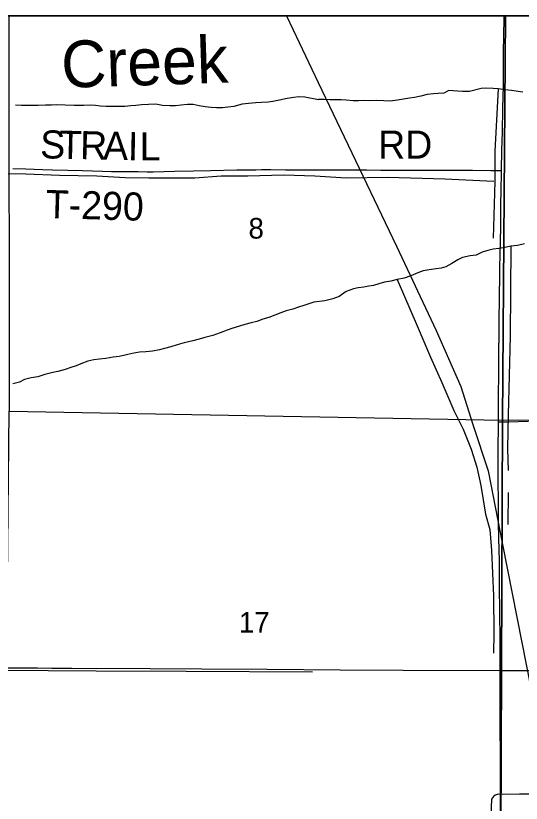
# Model space of a CAD drawing. Extents: x 0 to 34, y 0 to 22.
# Drawn here: x 2.522 to 3.546, y 19.306 to 20.9 of the extents above; entities that cross this region are included whole.
import ezdxf

# ---------------------------------------------------------------- set-up
doc = ezdxf.new("R2010")
doc.units = 0
for name, color, linetype in [('GM_X_City_Street', 7, 'Continuous'), ('GM_X_County_Road', 7, 'Continuous'), ('GM_X_Minor_River', 7, 'Continuous'), ('GM_X_Minor_River_Text', 7, 'Continuous'), ('GM_X_Rail_Line', 7, 'Continuous'), ('GM_X_Section', 7, 'Continuous'), ('GM_X_Section_Text', 7, 'Continuous'), ('GM_X_Township_Road', 7, 'Continuous'), ('GM_X_Township_Road_Text', 7, 'Continuous'), ('GM_X_US_Route', 7, 'Continuous'), ('SH_Cut_Line', 7, 'Continuous'), ('SH_Data', 7, 'Continuous')]:
    doc.layers.add(name, color=color, linetype=linetype)

msp = doc.modelspace()

# ---------------------------------------------------------------- linework, layer by layer
at = {"layer": 'GM_X_City_Street'}
for points in [[(3.5146, 20.9), (2.5083, 20.9), (2.509, 20.0994), (3.5083, 20.0811)], [(4.528, 20.9), (3.5146, 20.9), (3.5083, 20.0811), (4.5187, 20.0828)]]:
    msp.add_lwpolyline(points, close=True, dxfattribs=at)
at = {"layer": 'GM_X_County_Road'}
for points in [[(3.5065, 20.5865), (3.5072, 20.628), (3.5081, 20.6646), (3.5093, 20.7131), (3.5101, 20.7579), (3.5102, 20.7791), (3.5104, 20.8002), (3.5107, 20.8313), (3.511, 20.8549), (3.5119, 20.9)], [(3.5002, 20.078), (3.5002, 20.0911), (3.5006, 20.1446), (3.5007, 20.1608), (3.5008, 20.1788), (3.501, 20.2242), (3.5014, 20.2509), (3.5018, 20.2926), (3.5021, 20.3187), (3.503, 20.3868), (3.5039, 20.4197), (3.5043, 20.4409), (3.5047, 20.4757), (3.5053, 20.5117), (3.5059, 20.5528), (3.5063, 20.5758), (3.5065, 20.5865)], [(3.5035, 19.5744), (3.5035, 19.5826), (3.5034, 19.6354), (3.5029, 19.6951), (3.5023, 19.7424), (3.5024, 19.7585), (3.5022, 19.7958), (3.5011, 19.8425), (3.5006, 19.8742), (3.5001, 19.904), (3.4997, 19.9712), (3.4999, 20.0302), (3.5001, 20.0644), (3.5002, 20.078)], [(3.5048, 19.0707), (3.5048, 19.0947), (3.5048, 19.104), (3.5048, 19.173), (3.5048, 19.2159), (3.5047, 19.2551), (3.5045, 19.2887), (3.5044, 19.3154), (3.5042, 19.3353), (3.504, 19.3713), (3.504, 19.408), (3.5037, 19.4559), (3.5038, 19.4764), (3.5035, 19.5168), (3.5037, 19.5347), (3.5035, 19.5565), (3.5035, 19.5744)]]:
    msp.add_lwpolyline(points, dxfattribs=at)
at = {"layer": 'GM_X_Minor_River'}
for points in [[(3.5496, 20.7454), (3.5269, 20.7486), (3.5133, 20.7501), (3.4997, 20.7519), (3.4892, 20.7529), (3.4748, 20.7537), (3.4649, 20.7524), (3.4413, 20.7469), (3.4273, 20.7468), (3.4174, 20.7475), (3.3997, 20.7487), (3.3897, 20.7436), (3.3783, 20.7423), (3.3688, 20.7418), (3.3555, 20.7406), (3.343, 20.7371), (3.33, 20.7344), (3.3198, 20.7331), (3.2954, 20.7292), (3.281, 20.7272), (3.2681, 20.7279), (3.2534, 20.7283), (3.2397, 20.7279), (3.2272, 20.7282), (3.217, 20.7276), (3.206, 20.7275), (3.1917, 20.7294), (3.1814, 20.7296), (3.1712, 20.7295), (3.1587, 20.7298), (3.147, 20.7305), (3.136, 20.7307)], [(3.4997, 20.7519), (3.4928, 20.6257), (3.4928, 20.5646), (3.4896, 20.4501)], [(2.5221, 20.7194), (2.5342, 20.7187), (2.5463, 20.7187), (2.5581, 20.7191), (2.5676, 20.7188), (2.5828, 20.7195), (2.5946, 20.72), (2.6041, 20.7201), (2.6405, 20.719), (2.6507, 20.7191), (2.6602, 20.7192), (2.6732, 20.7196), (2.6841, 20.7189), (2.694, 20.7179), (2.7053, 20.7168), (2.7182, 20.7168), (2.7338, 20.7167), (2.7437, 20.7168), (2.7559, 20.718), (2.7658, 20.7189), (2.7779, 20.7204), (2.7913, 20.7212), (2.8065, 20.7219), (2.82, 20.7188), (2.8348, 20.718), (2.8462, 20.7184), (2.8576, 20.7196), (2.8706, 20.7212), (2.8816, 20.7208), (2.8937, 20.7182), (2.9061, 20.7163), (2.9186, 20.7152), (2.9292, 20.7145), (2.9414, 20.7146), (2.952, 20.7154), (2.9646, 20.7173), (2.9818, 20.7218), (2.994, 20.7233), (3.0085, 20.7241), (3.0203, 20.7252), (3.0336, 20.7256), (3.0435, 20.7272), (3.0565, 20.7299), (3.0721, 20.7333), (3.0859, 20.7355), (3.0958, 20.7368), (3.1082, 20.7356), (3.136, 20.7307)], [(3.1282, 20.5752), (3.0655, 20.5771), (2.9928, 20.5751), (2.9386, 20.5755), (2.8853, 20.5713), (2.8318, 20.5713), (2.7919, 20.571), (2.7441, 20.5719), (2.6865, 20.5751), (2.6114, 20.5765), (2.5431, 20.5796), (2.4987, 20.5797), (2.4415, 20.5289), (2.224, 20.5306), (2.1, 20.5313)], [(3.4905, 20.5647), (3.3914, 20.569), (3.2764, 20.5729), (3.1915, 20.5711), (3.1282, 20.5752)], [(3.5529, 20.4383), (3.5388, 20.4352), (3.5255, 20.4336), (3.5107, 20.4302), (3.5008, 20.4286), (3.4894, 20.4273), (3.4784, 20.4245), (3.4673, 20.4214), (3.455, 20.4156), (3.4429, 20.414), (3.4273, 20.4106), (3.4177, 20.4059), (3.4058, 20.3986), (3.3938, 20.3917), (3.3839, 20.3893), (3.3737, 20.3876), (3.36, 20.3857), (3.3478, 20.3837), (3.3367, 20.3798), (3.3229, 20.3733), (3.3092, 20.3687), (3.2947, 20.3664), (3.2825, 20.3629), (3.2692, 20.3609), (3.2582, 20.357), (3.2471, 20.3539), (3.2376, 20.3526)], [(3.5255, 20.4336), (3.5237, 20.2511), (3.5201, 20.0922), (3.5188, 20.0243), (3.5199, 19.9795)], [(3.2947, 20.3664), (3.3356, 20.2724), (3.3628, 20.2087), (3.3854, 20.1577), (3.4097, 20.101), (3.4289, 20.0629), (3.4449, 20.0227), (3.4561, 19.9864), (3.4643, 19.949), (3.4742, 19.891), (3.4825, 19.8601), (3.4864, 19.8175), (3.4898, 19.7259), (3.4905, 19.6493), (3.4899, 19.6094)], [(3.2376, 20.3526), (3.2273, 20.3509), (3.2163, 20.3489), (3.2068, 20.3469), (3.1919, 20.3415), (3.1776, 20.332), (3.165, 20.3273), (3.1483, 20.3232), (3.126, 20.3199)], [(3.126, 20.3199), (3.1164, 20.3168), (3.1057, 20.3137), (3.095, 20.3098), (3.0835, 20.3063), (3.0701, 20.3025), (3.0597, 20.2986), (3.0471, 20.2937), (3.0348, 20.2895), (3.0229, 20.2856), (3.0107, 20.2814), (2.9996, 20.2787), (2.9862, 20.2749), (2.9755, 20.2718), (2.9601, 20.2669), (2.9505, 20.2634), (2.9364, 20.2581), (2.9218, 20.2528), (2.9053, 20.2487), (2.8942, 20.2456), (2.8812, 20.2422), (2.8636, 20.2377), (2.8495, 20.2336), (2.8365, 20.2301), (2.8239, 20.2267), (2.8135, 20.224), (2.7998, 20.2213), (2.7861, 20.2194), (2.7731, 20.2187), (2.7583, 20.2164), (2.7468, 20.2137), (2.7319, 20.2103), (2.7197, 20.2088), (2.7052, 20.2065), (2.6919, 20.205), (2.6805, 20.2034), (2.6682, 20.2008), (2.6544, 20.1951), (2.6448, 20.1915), (2.6341, 20.1877), (2.6226, 20.1838), (2.6077, 20.1801), (2.5973, 20.1777), (2.5817, 20.1736), (2.5675, 20.1694), (2.5534, 20.1668), (2.54, 20.1634), (2.5304, 20.1583), (2.5166, 20.1549)], [(3.52, 19.9351), (3.5195, 19.8702)], [(3.1233, 19.571), (2.8675, 19.5726), (2.6853, 19.5733), (2.4909, 19.5747), (2.3688, 19.5767), (2.1601, 19.5815), (2.1, 19.5823)], [(3.5703, 19.324), (3.5427, 19.3243), (3.5078, 19.3236), (3.4999, 19.3242), (3.4938, 19.3224), (3.4903, 19.3195), (3.4864, 19.3143), (3.4816, 19.1971)]]:
    msp.add_lwpolyline(points, dxfattribs=at)
at = {"layer": 'GM_X_Rail_Line'}
msp.add_lwpolyline([(3.0707, 20.9), (3.1351, 20.7649), (3.2934, 20.4339), (3.3742, 20.2628), (3.4243, 20.1498), (3.4485, 20.0723), (3.4792, 19.9786), (3.5083, 19.83), (3.6846, 18.9371), (3.8463, 18.1103), (4.0848, 16.8935)], dxfattribs=at)
at = {"layer": 'GM_X_Section'}
for points in [[(2.509, 20.0994), (3.5083, 20.0811), (3.5044, 19.0749), (2.4993, 19.0815)], [(4.5187, 20.0828), (4.5106, 19.0706), (3.5044, 19.0749), (3.5083, 20.0811)]]:
    msp.add_lwpolyline(points, close=True, dxfattribs=at)
at = {"layer": 'GM_X_Township_Road'}
for points in [[(2.5165, 20.5907), (2.5426, 20.5899), (2.5767, 20.5889), (2.5972, 20.5884), (2.6575, 20.5867), (2.6985, 20.5853), (2.7165, 20.5847), (2.7482, 20.5844), (2.7706, 20.5844), (2.7887, 20.5841), (2.8011, 20.5843), (2.844, 20.5853), (2.8825, 20.5861), (2.9167, 20.5868), (2.9702, 20.5882), (2.9894, 20.5884), (3.0087, 20.5884), (3.0205, 20.5885), (3.0392, 20.5886), (3.0691, 20.5883), (3.0963, 20.5882), (3.1672, 20.5881), (3.2057, 20.5879), (3.2331, 20.5879), (3.2617, 20.5876), (3.289, 20.5874), (3.3145, 20.5876), (3.4128, 20.5873), (3.4476, 20.5875), (3.4849, 20.587), (3.5034, 20.5866), (3.5065, 20.5865)], [(3.5002, 20.078), (3.5019, 20.078), (3.5189, 20.0783), (3.5608, 20.079)], [(2.5062, 19.5803), (2.5415, 19.5799), (2.5664, 19.5798), (2.5956, 19.5796), (2.636, 19.5795), (2.7946, 19.5788), (2.8996, 19.5781), (3.0315, 19.5773), (3.1795, 19.5762), (3.3069, 19.5754), (3.5035, 19.5744)], [(3.5035, 19.5744), (3.5059, 19.5744), (3.5793, 19.5747), (3.675, 19.5755), (3.7322, 19.5757), (3.8062, 19.5765), (3.9157, 19.5771), (4.0089, 19.5777), (4.0406, 19.5779), (4.0947, 19.578), (4.2135, 19.5787), (4.2763, 19.5792), (4.3864, 19.5799), (4.4865, 19.5805), (4.5039, 19.5804), (4.5106, 19.5804)]]:
    msp.add_lwpolyline(points, dxfattribs=at)
at = {"layer": 'GM_X_US_Route'}
msp.add_lwpolyline([(7.5667, 20.9), (2.1, 20.9)], dxfattribs=at)
at = {"layer": 'SH_Cut_Line'}
msp.add_lwpolyline([(7.5667, 20.9), (2.1, 20.9), (2.1, 14.1)], dxfattribs=at)
at = {"layer": 'SH_Data'}
msp.add_line((2.1, 20.9), (8.9, 20.9), dxfattribs=at)

# ---------------------------------------------------------------- texts
at = {"layer": 'GM_X_Minor_River_Text'}
msp.add_text('Creek', height=0.09476, rotation=1.8544, dxfattribs=at).set_placement((2.616, 20.7538))
at = {"layer": 'GM_X_Section_Text'}
for s, height, p in [('8', 0.0419, (2.9939, 20.4489)), ('17', 0.04186, (2.9744, 19.6511))]:
    msp.add_text(s, height=height, rotation=0, dxfattribs=at).set_placement(p)
at = {"layer": 'GM_X_Township_Road_Text'}
for s, height, rotation, p in [('S', 0.0568, 358.755, (2.5715, 20.6116)), ('T', 0.0568, 358.7567, (2.6098, 20.6108)), ('R', 0.0568, 358.7549, (2.6523, 20.6099)), ('A', 0.0568, 358.7595, (2.699, 20.6089)), ('I', 0.0568, 358.8542, (2.7491, 20.6078)), ('L', 0.0568, 0.0066, (2.7736, 20.6073)), ('RD', 0.05682, 0, (3.2564, 20.6108)), ('T-290', 0.05682, 358.3195, (2.5826, 20.4907))]:
    msp.add_text(s, height=height, rotation=rotation, dxfattribs=at).set_placement(p)

doc.saveas('drawing.dxf')
